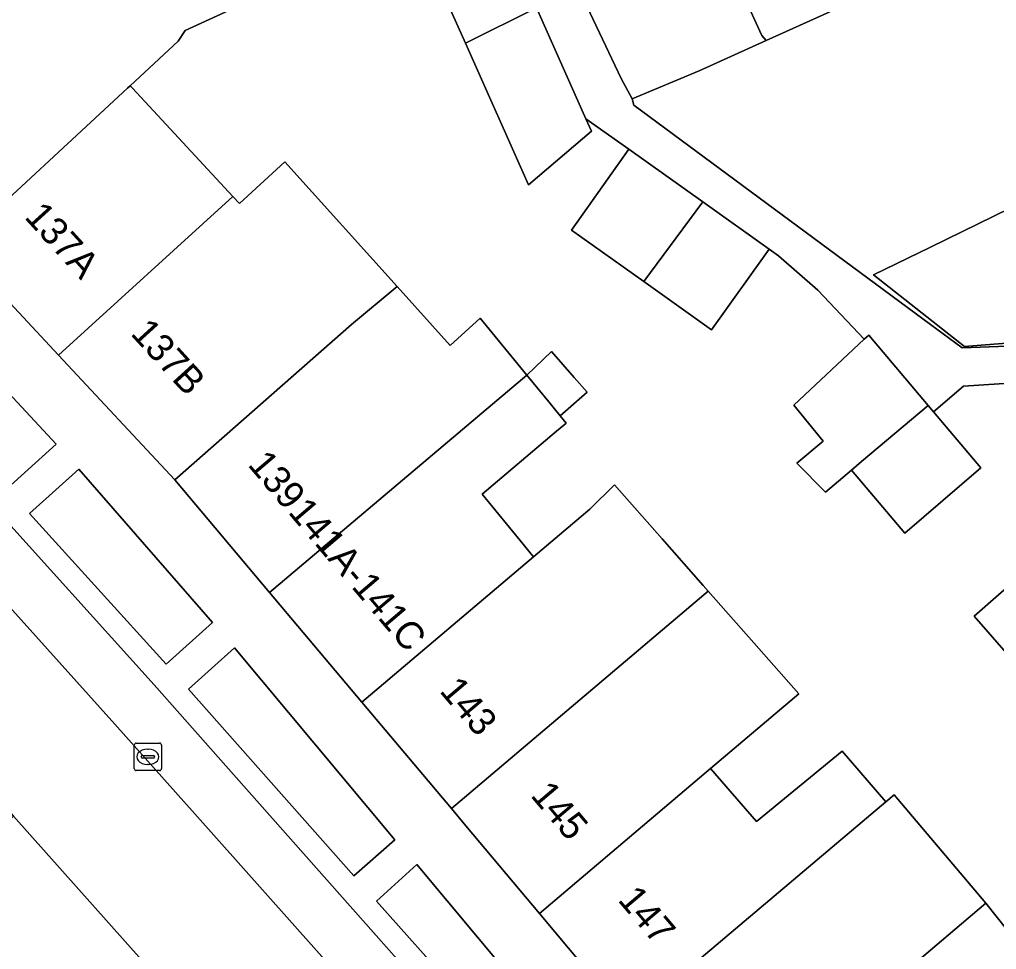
# Model space of a CAD drawing. Extents: x 159888 to 160761, y 384031 to 384750.
# Drawn here: x 160438.55 to 160474.19, y 384395.65 to 384429.58 of the extents above; entities that cross this region are included whole.
import ezdxf

# ---------------------------------------------------------------- set-up
doc = ezdxf.new("R2010")
doc.units = 0
for name, color, linetype in [('IMGEO_Erf', 7, 'Continuous'), ('IMGEO_Groenvoorziening', 7, 'Continuous'), ('IMGEO_Kolk', 7, 'Continuous'), ('IMGEO_Pand', 7, 'Continuous'), ('IMGEO_Pand_nummerreeks', 7, 'Continuous'), ('IMGEO_Parkeervlak_open', 7, 'Continuous'), ('IMGEO_Rijbaan_lokaal_open', 7, 'Continuous'), ('IMGEO_Voetpad_open', 7, 'Continuous')]:
    doc.layers.add(name, color=color, linetype=linetype)

msp = doc.modelspace()

# ---------------------------------------------------------------- linework, layer by layer
at = {"layer": 'IMGEO_Erf'}
for points in [[(160478.187, 384416.544), (160472.991, 384416.207), (160471.887, 384415.274), (160473.621, 384413.22), (160470.845, 384410.842), (160468.9, 384413.145), (160467.946, 384412.338), (160466.911, 384413.392), (160467.867, 384414.193), (160466.8, 384415.508), (160469.367, 384417.92), (160467.666, 384419.705), (160466.242, 384420.956), (160465.896, 384421.203), (160463.798, 384418.258), (160461.319, 384420.023), (160458.681, 384421.902), (160460.778, 384424.847), (160459.209, 384425.964), (160459.411, 384425.511), (160457.121, 384423.549), (160454.815, 384428.715), (160452.913, 384432.978)], [(160448.254, 384430.872), (160444.591, 384429.182), (160444.334, 384428.795), (160442.579, 384427.165), (160442.664, 384427.073), (160446.326, 384423.13), (160446.568, 384422.87), (160448.232, 384424.385), (160452.32, 384419.845), (160454.258, 384417.693), (160455.358, 384418.684), (160457.057, 384416.606), (160457.953, 384417.467), (160458.786, 384416.52), (160459.255, 384415.988), (160458.271, 384415.121), (160458.491, 384414.852), (160458.408, 384414.781), (160458.143, 384414.558), (160455.43, 384412.267), (160456.926, 384410.436), (160457.179, 384410.126), (160457.3, 384409.978), (160459.357, 384411.717), (160460.255, 384412.611), (160461.996, 384410.634), (160463.493, 384408.934), (160463.676, 384408.726), (160465.341, 384406.836), (160466.972, 384404.984), (160463.754, 384402.258), (160465.433, 384400.327), (160468.56, 384402.89), (160470.147, 384401.042), (160470.453, 384401.301), (160473.796, 384397.347), (160475.687, 384394.966)], [(160468.114, 384429.864), (160465.784, 384428.812), (160463.343, 384427.71), (160460.892, 384426.684), (160460.957, 384426.457), (160471.783, 384418.455), (160472.937, 384417.602), (160477.23, 384417.765), (160478.66, 384417.902), (160481.72, 384419.27), (160486.13, 384421.264), (160486.351, 384421.37), (160484.568, 384425.214), (160489.455, 384427.481), (160491.204, 384423.709), (160495.702, 384425.876), (160496.507, 384424.091), (160507.911, 384429.24)]]:
    msp.add_lwpolyline(points, dxfattribs=at)
for points in [[(160481.72, 384419.27), (160478.13, 384418.054), (160477.01, 384417.965), (160473.017, 384417.65), (160469.705, 384420.264), (160471.786, 384421.281), (160474.685, 384422.698), (160475.427, 384421.189), (160479.867, 384423.248)], [(160473.374, 384407.813), (160476.033, 384410.147), (160478.047, 384407.854), (160475.387, 384405.519)]]:
    msp.add_lwpolyline(points, close=True, dxfattribs=at)
at = {"layer": 'IMGEO_Groenvoorziening'}
for points in [[(160438.091, 384412.475), (160439.887, 384414.094), (160435.003, 384419.326), (160433.291, 384417.804)], [(160443.9, 384406.065), (160445.586, 384407.579), (160440.713, 384413.174), (160438.912, 384411.555)], [(160450.744, 384398.334), (160452.241, 384399.649), (160446.389, 384406.654), (160444.712, 384405.146)], [(160457.383, 384390.899), (160458.639, 384392.047), (160453.039, 384398.751), (160451.573, 384397.411)]]:
    msp.add_lwpolyline(points, close=True, dxfattribs=at)
at = {"layer": 'IMGEO_Kolk'}
for p, q in [((160442.804, 384403.182), (160443.656, 384403.182)), ((160442.729, 384402.256), (160442.729, 384403.108)), ((160443.217, 384402.962), (160443.242, 384402.962)), ((160443.73, 384403.108), (160443.73, 384402.256)), ((160442.988, 384402.676), (160442.988, 384402.688)), ((160443.426, 384402.639), (160443.028, 384402.639)), ((160443.031, 384402.725), (160443.429, 384402.725)), ((160443.472, 384402.688), (160443.472, 384402.676)), ((160443.656, 384402.182), (160442.804, 384402.182)), ((160443.24, 384402.402), (160443.215, 384402.402))]:
    msp.add_line(p, q, dxfattribs=at)
for points in [[(160442.804, 384403.182), (160443.656, 384403.182)], [(160442.729, 384402.256), (160442.729, 384403.108)], [(160443.73, 384403.108), (160443.73, 384402.256)], [(160443.656, 384402.182), (160442.804, 384402.182)]]:
    msp.add_lwpolyline(points, dxfattribs=at)
for centre, radius, start, end in [((160442.806, 384403.106), 0.0765, 91.552, 178.448), ((160442.806, 384403.106), 0.0765, 91.552, 178.448), ((160443.654, 384403.106), 0.0765, 1.552, 88.448), ((160443.654, 384403.106), 0.0765, 1.552, 88.448), ((160443.028, 384402.685), 0.0403, 85.8775, 175.7526), ((160443.025, 384402.675), 0.0366, 178.938, 274.7102), ((160443.429, 384402.682), 0.043, 264.8664, 352.4533), ((160443.433, 384402.687), 0.0386, 1.7309, 96.639), ((160442.806, 384402.258), 0.0765, 181.552, 268.448), ((160442.806, 384402.258), 0.0765, 181.552, 268.448), ((160443.654, 384402.258), 0.0765, 271.552, 358.448), ((160443.654, 384402.258), 0.0765, 271.552, 358.448)]:
    msp.add_arc(centre, radius, start, end, dxfattribs=at)
for centre, major_axis, ratio, start_param, end_param in [((160443.216, 384402.682), (-0.387, 0.002), 0.722429, 4.712389, 7.853982), ((160443.241, 384402.682), (-0.39, 0.002), 0.717154, 1.570796, 4.712389)]:
    msp.add_ellipse(centre, major_axis=major_axis, ratio=ratio, start_param=start_param, end_param=end_param, dxfattribs=at)
at = {"layer": 'IMGEO_Pand'}
for points in [[(160465.01, 384442.85), (160460.276, 384440.681), (160465.625, 384428.999), (160465.784, 384428.812), (160468.114, 384429.864), (160466.757, 384432.868), (160469.101, 384433.926)], [(160460.276, 384440.681), (160455.382, 384438.439), (160457.439, 384433.882), (160460.493, 384427.436), (160460.892, 384426.684), (160463.343, 384427.71), (160465.784, 384428.812), (160465.625, 384428.999)], [(160442.489, 384427.081), (160442.579, 384427.165), (160444.334, 384428.795), (160444.591, 384429.182), (160448.254, 384430.872), (160451.074, 384432.172), (160452.913, 384432.978), (160454.815, 384428.715), (160457.405, 384430.008), (160455.56, 384434.139), (160453.93, 384437.792), (160447.309, 384434.839), (160439.345, 384431.166), (160433.504, 384425.741), (160433.519, 384424.249), (160436.258, 384421.313)], [(160459.209, 384425.964), (160457.405, 384430.008), (160454.815, 384428.715), (160457.121, 384423.549), (160459.411, 384425.511)], [(160446.326, 384423.13), (160442.664, 384427.073), (160442.579, 384427.165), (160442.489, 384427.081), (160436.258, 384421.313), (160439.967, 384417.341)], [(160463.474, 384422.928), (160460.778, 384424.847), (160458.681, 384421.902), (160461.319, 384420.023)], [(160452.32, 384419.845), (160448.232, 384424.385), (160446.568, 384422.87), (160446.326, 384423.13), (160439.967, 384417.341), (160444.212, 384412.794), (160450.664, 384418.46)], [(160465.896, 384421.203), (160463.474, 384422.928), (160461.319, 384420.023), (160463.798, 384418.258)], [(160475.427, 384421.189), (160474.685, 384422.698), (160471.786, 384421.281), (160469.705, 384420.264), (160473.017, 384417.65), (160477.01, 384417.965)], [(160457.057, 384416.606), (160455.358, 384418.684), (160454.258, 384417.693), (160452.32, 384419.845), (160450.664, 384418.46), (160444.212, 384412.794), (160447.666, 384408.676)], [(160469.367, 384417.92), (160466.8, 384415.508), (160467.867, 384414.193), (160466.911, 384413.392), (160467.946, 384412.338), (160468.9, 384413.145), (160469.268, 384413.456), (160471.691, 384415.506), (160469.527, 384418.07)], [(160457.057, 384416.606), (160457.854, 384415.632), (160458.271, 384415.121), (160459.255, 384415.988), (160458.786, 384416.52), (160457.953, 384417.467)], [(160456.926, 384410.436), (160455.43, 384412.267), (160458.143, 384414.558), (160458.408, 384414.781), (160458.491, 384414.852), (160458.271, 384415.121), (160457.854, 384415.632), (160457.057, 384416.606), (160447.666, 384408.676), (160448.892, 384407.214), (160451.03, 384404.677), (160457.3, 384409.978), (160457.179, 384410.126)], [(160471.887, 384415.274), (160471.691, 384415.506), (160469.268, 384413.456), (160468.9, 384413.145), (160470.845, 384410.842), (160473.621, 384413.22)], [(160463.676, 384408.726), (160463.493, 384408.934), (160461.996, 384410.634), (160460.255, 384412.611), (160459.357, 384411.717), (160457.3, 384409.978), (160451.03, 384404.677), (160454.301, 384400.796)], [(160473.374, 384407.813), (160475.387, 384405.519), (160478.047, 384407.854), (160476.033, 384410.147)], [(160466.972, 384404.984), (160465.341, 384406.836), (160463.676, 384408.726), (160454.301, 384400.796), (160454.828, 384400.17), (160457.512, 384396.97), (160463.754, 384402.258)], [(160470.147, 384401.042), (160468.56, 384402.89), (160465.433, 384400.327), (160463.754, 384402.258), (160457.512, 384396.97), (160460.756, 384393.102)], [(160473.796, 384397.347), (160470.453, 384401.301), (160470.147, 384401.042), (160460.756, 384393.102), (160462.464, 384391.065), (160464.11, 384389.113)], [(160477.438, 384392.814), (160475.687, 384394.966), (160473.796, 384397.347), (160464.11, 384389.113), (160464.471, 384388.685), (160467.825, 384384.686), (160474.666, 384390.47)]]:
    msp.add_lwpolyline(points, close=True, dxfattribs=at)
at = {"layer": 'IMGEO_Parkeervlak_open'}
for points in [[(160456.093, 384391.043), (160446.447, 384401.928), (160443.46, 384405.305), (160431.217, 384418.885)], [(160429.41, 384417.903), (160442.025, 384403.87), (160444.943, 384400.6), (160454.605, 384389.746)]]:
    msp.add_lwpolyline(points, dxfattribs=at)
at = {"layer": 'IMGEO_Rijbaan_lokaal_open'}
for points in [[(160429.41, 384417.903), (160429.048, 384418.276), (160428.681, 384418.655), (160424.938, 384415.361), (160437.188, 384401.812), (160438.333, 384400.522), (160442.998, 384395.269), (160450.604, 384386.752), (160452.124, 384384.998), (160459.404, 384376.559), (160460.141, 384375.69), (160468.022, 384365.99)], [(160454.605, 384389.746), (160444.943, 384400.6), (160442.025, 384403.87), (160429.41, 384417.903)]]:
    msp.add_lwpolyline(points, dxfattribs=at)
at = {"layer": 'IMGEO_Voetpad_open'}
for points in [[(160477.23, 384417.765), (160472.937, 384417.602), (160471.783, 384418.455), (160460.957, 384426.457), (160460.892, 384426.684), (160460.493, 384427.436), (160457.439, 384433.882)], [(160457.405, 384430.008), (160459.209, 384425.964), (160460.778, 384424.847), (160463.474, 384422.928), (160465.896, 384421.203), (160466.242, 384420.956), (160467.666, 384419.705), (160469.367, 384417.92), (160469.527, 384418.07), (160471.691, 384415.506), (160471.887, 384415.274), (160472.991, 384416.207), (160478.187, 384416.544)], [(160454.828, 384400.17), (160454.301, 384400.796), (160451.03, 384404.677), (160448.892, 384407.214), (160447.666, 384408.676), (160444.212, 384412.794), (160439.967, 384417.341), (160436.258, 384421.313), (160433.519, 384424.249), (160430.268, 384427.625), (160428.687, 384429.27)], [(160442.998, 384395.269), (160438.333, 384400.522), (160436.685, 384399.036), (160435.35, 384400.485), (160435.387, 384400.801), (160424.012, 384413.426), (160422.846, 384414.697), (160419.209, 384418.662), (160420.429, 384419.757), (160415.207, 384425.228)], [(160427.528, 384419.982), (160430.451, 384422.7), (160432.634, 384420.365), (160431.306, 384419.153), (160431.217, 384418.885), (160443.46, 384405.305), (160446.447, 384401.928), (160456.093, 384391.043)], [(160469.271, 384372.522), (160473.675, 384366.69), (160474.24, 384368.231), (160476.896, 384370.172), (160478.279, 384371.695), (160477.728, 384372.628), (160477.501, 384373.013), (160475.174, 384375.922), (160471.413, 384380.406), (160467.825, 384384.686), (160464.471, 384388.685), (160464.11, 384389.113), (160462.464, 384391.065), (160460.756, 384393.102), (160457.512, 384396.97), (160454.828, 384400.17)]]:
    msp.add_lwpolyline(points, dxfattribs=at)
for points in [[(160438.091, 384412.475), (160433.291, 384417.804), (160435.003, 384419.326), (160439.887, 384414.094)], [(160443.9, 384406.065), (160438.912, 384411.555), (160440.713, 384413.174), (160445.586, 384407.579)], [(160450.744, 384398.334), (160444.712, 384405.146), (160446.389, 384406.654), (160452.241, 384399.649)], [(160453.039, 384398.751), (160458.639, 384392.047), (160457.383, 384390.899), (160451.573, 384397.411)]]:
    msp.add_lwpolyline(points, close=True, dxfattribs=at)

# ---------------------------------------------------------------- texts
at = {"layer": 'IMGEO_Pand_nummerreeks'}
for s, rotation, p in [('137A', 312.3127, (160438.694, 384422.36)), ('137B', 312.3299, (160442.567, 384418.105)), ('139', 310.3131, (160446.844, 384413.329)), ('141A-141C', 310.3761, (160448.315, 384411.598)), ('143', 310.2443, (160453.839, 384405.073)), ('145', 310.2443, (160457.16, 384401.261)), ('147', 310.2443, (160460.345, 384397.449))]:
    msp.add_text(s, height=1, rotation=rotation, dxfattribs=at).set_placement(p)

doc.saveas('drawing.dxf')
